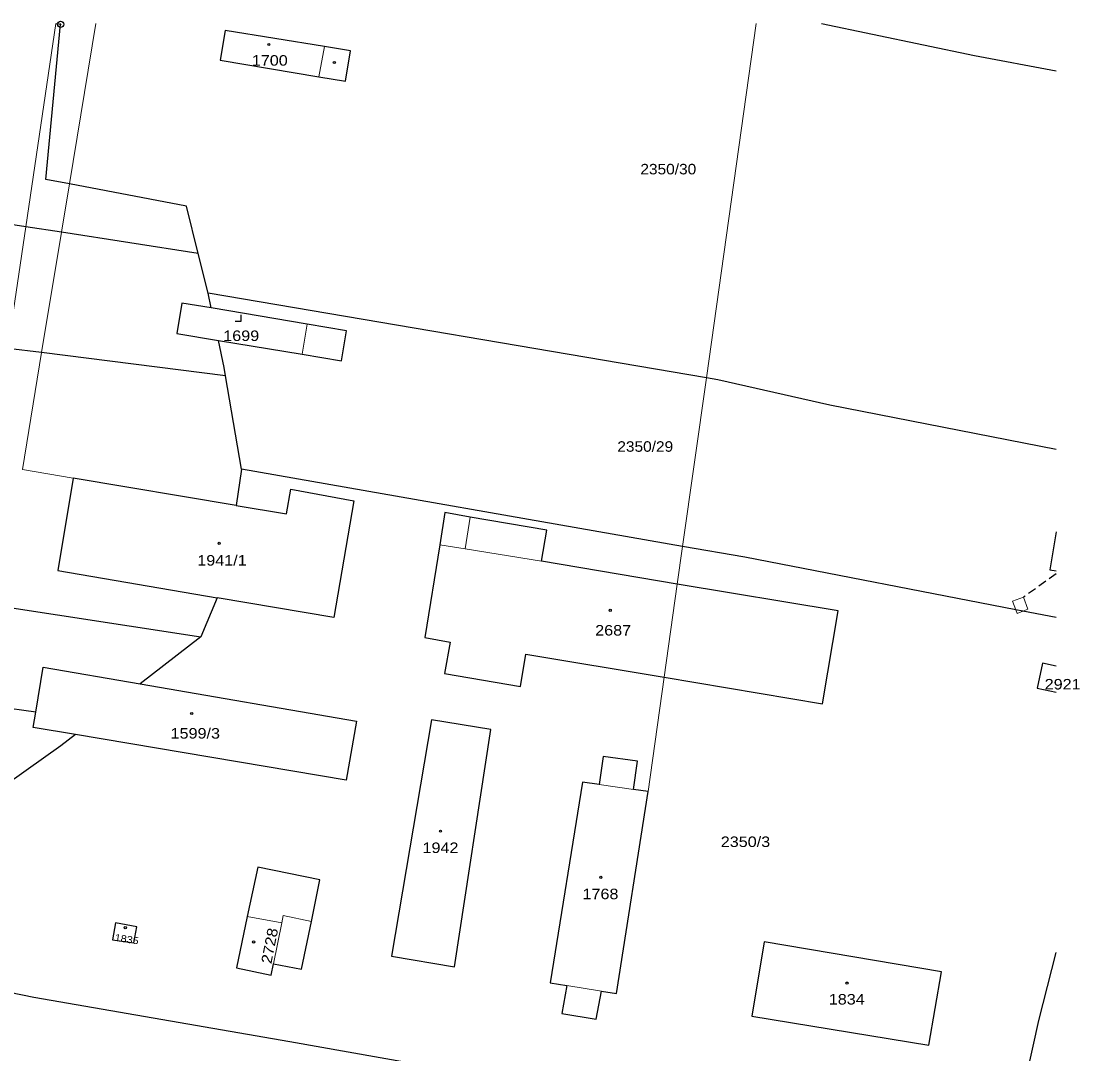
# Model space of a CAD drawing. Extents: x -652394 to -652006, y -1024262 to -1023975.
# Drawn here: x -652176.9 to -652005.6, y -1024142.7 to -1023975.5 of the extents above; entities that cross this region are included whole.
import ezdxf

# ---------------------------------------------------------------- set-up
doc = ezdxf.new("R2010")
doc.units = 0
doc.header["$LTSCALE"] = 0.46
doc.linetypes.add('MEDIUM_DASHED', pattern=[4.5, 3, -1.5])
doc.layers.add('63', color=7, linetype='Continuous', lineweight=25)

msp = doc.modelspace()

# ---------------------------------------------------------------- linework, layer by layer
at = {"layer": '63', "lineweight": 13}
for p, q in [((-652176.19, -1024008.82), (-652171.333, -1023975.941)), ((-652169.11, -1024001.89), (-652164.834, -1023975.941)), ((-652066.03, -1024033.3), (-652057.952, -1023975.941)), ((-652128.74, -1023984.54), (-652127.84, -1023979.66)), ((-652170.4, -1024009.72), (-652169.11, -1024001.89)), ((-652179.1, -1024028.51), (-652176.19, -1024008.82)), ((-652131.45, -1024029.47), (-652130.66, -1024024.59)), ((-652069.87, -1024060.56), (-652066.03, -1024033.3)), ((-652176.73, -1024048.12), (-652168.53, -1024049.53)), ((-652105.08, -1024060.94), (-652092.7, -1024062.94)), ((-652070.73, -1024066.65), (-652069.87, -1024060.56)), ((-652072.86, -1024081.74), (-652070.73, -1024066.65)), ((-652016.48, -1024069.45), (-652014.7, -1024068.79)), ((-652016.48, -1024069.45), (-652015.97, -1024070.81)), ((-652014.7, -1024068.79), (-652013.98, -1024070.71)), ((-652014.8, -1024071.04), (-652013.98, -1024070.71)), ((-652075.46, -1024100.21), (-652072.86, -1024081.74)), ((-652083.38, -1024099.11), (-652077.81, -1024099.89)), ((-652140.32, -1024120.48), (-652134.75, -1024121.52)), ((-652136.08, -1024128.14), (-652134.75, -1024121.52)), ((-652088.63, -1024131.64), (-652083.02, -1024132.53))]:
    msp.add_line(p, q, dxfattribs=at)
at = {"layer": '63'}
for p, q in [((-652171.192, -1023975.941), (-652170.54, -1023976.04)), ((-652170.54, -1023976.04), (-652170.53, -1023975.941)), ((-652146.66, -1024019.59), (-652148.27, -1024013.13)), ((-652146.15, -1024021.97), (-652146.66, -1024019.59)), ((-652141.25, -1024048.05), (-652143.83, -1024032.94)), ((-652142.12, -1024053.95), (-652133.96, -1024055.31)), ((-652009.403, -1024058.19), (-652010.45, -1024064.33)), ((-652010.45, -1024064.33), (-652009.403, -1024064.501)), ((-652126.33, -1024072.09), (-652145.21, -1024068.87)), ((-652174.55, -1024087.4), (-652190.57, -1024085.1))]:
    msp.add_line(p, q, dxfattribs=at)
at = {"layer": '63', "linetype": 'MEDIUM_DASHED'}
msp.add_line((-652009.403, -1024064.997), (-652014.7, -1024068.79), dxfattribs=at)
at = {"layer": '63'}
for points in [[(-652148.27, -1024013.13), (-652170.4, -1024009.72), (-652176.19, -1024008.82), (-652243.97, -1023998.36), (-652254.55, -1023996.87), (-652255.534, -1023975.941)], [(-652148.27, -1024013.13), (-652150.18, -1024005.47), (-652169.11, -1024001.89), (-652172.93, -1024001.16), (-652170.54, -1023976.04)], [(-652047.402, -1023975.941), (-652022.66, -1023981.11), (-652009.403, -1023983.604)], [(-652143.83, -1024032.94), (-652173.61, -1024029.2), (-652179.1, -1024028.51), (-652205.95, -1024025.14), (-652253.52, -1024018.67)], [(-652009.403, -1024044.899), (-652046.04, -1024037.7), (-652064.17, -1024033.62), (-652066.03, -1024033.3), (-652146.66, -1024019.59)], [(-652146.15, -1024021.97), (-652150.9, -1024021.17), (-652151.72, -1024026.09), (-652145.01, -1024027.21)], [(-652145.01, -1024027.21), (-652131.45, -1024029.47), (-652125.06, -1024030.53), (-652124.28, -1024025.67), (-652130.66, -1024024.59), (-652146.15, -1024021.97)], [(-652142.301, -1024024.08), (-652141.3, -1024024.08), (-652141.3, -1024023.08)], [(-652143.83, -1024032.94), (-652144.06, -1024031.61), (-652145.01, -1024027.21)], [(-652009.403, -1024072.085), (-652014.8, -1024071.04), (-652015.97, -1024070.81), (-652059.83, -1024062.32), (-652069.87, -1024060.56), (-652141.25, -1024048.05), (-652142.12, -1024053.95)], [(-652142.12, -1024053.95), (-652168.53, -1024049.53), (-652171.01, -1024064.48), (-652145.21, -1024068.87)], [(-652133.96, -1024055.31), (-652133.29, -1024051.32), (-652123.09, -1024053.17), (-652126.33, -1024072.09)], [(-652251.57, -1024060.11), (-652245.35, -1024060.77), (-652231.31, -1024062.37), (-652216.77, -1024064.61), (-652147.85, -1024075.21)], [(-652145.21, -1024068.87), (-652147.85, -1024075.21), (-652157.64, -1024082.83)], [(-652174.55, -1024087.4), (-652173.34, -1024080.12), (-652157.64, -1024082.83)], [(-652009.403, -1024079.928), (-652011.64, -1024079.45), (-652012.51, -1024083.5), (-652009.403, -1024084.169)], [(-652157.64, -1024082.83), (-652122.66, -1024088.87), (-652124.33, -1024098.39), (-652168.15, -1024091.02)], [(-652168.15, -1024091.02), (-652174.96, -1024089.87), (-652174.55, -1024087.4)], [(-652168.15, -1024091.02), (-652170.52, -1024092.87), (-652182.16, -1024101.09), (-652189.3, -1024108.53), (-652196.06, -1024116.16)], [(-652009.403, -1024157.766), (-652016.24, -1024155.4), (-652012.21, -1024137.29), (-652009.403, -1024126.324)], [(-652198.26, -1024128.72), (-652174.89, -1024133.55), (-652133.42, -1024140.71), (-652109.38, -1024144.99), (-652070.02, -1024157.71), (-652064.99, -1024159.32), (-652012.85, -1024174.11)]]:
    msp.add_lwpolyline(points, dxfattribs=at)
for points in [[(-652128.74, -1023984.54), (-652124.42, -1023985.27), (-652123.6, -1023980.35), (-652127.84, -1023979.66), (-652143.89, -1023977.05), (-652144.74, -1023981.85)], [(-652070.73, -1024066.65), (-652092.7, -1024062.94), (-652091.86, -1024057.95), (-652104.26, -1024055.81), (-652108.34, -1024055.1), (-652109.18, -1024060.29), (-652111.6, -1024075.33), (-652107.5, -1024076.04), (-652108.39, -1024081.16), (-652096.11, -1024083.25), (-652095.24, -1024078), (-652072.86, -1024081.74), (-652047.23, -1024086.02), (-652044.71, -1024070.97)], [(-652110.51, -1024088.61), (-652116.97, -1024126.91), (-652106.81, -1024128.64), (-652100.89, -1024090.21)], [(-652082.73, -1024094.57), (-652083.38, -1024099.11), (-652086.05, -1024098.75), (-652091.3, -1024131.22), (-652088.63, -1024131.64), (-652089.41, -1024136.19), (-652083.89, -1024137.11), (-652083.02, -1024132.53), (-652080.6, -1024132.91), (-652075.46, -1024100.21), (-652077.81, -1024099.89), (-652077.19, -1024095.35)], [(-652131.53, -1024129.02), (-652129.95, -1024121.27), (-652128.57, -1024114.51), (-652138.64, -1024112.49), (-652140.32, -1024120.48), (-652142.07, -1024128.8), (-652136.45, -1024129.95), (-652136.08, -1024128.14)], [(-652161.65, -1024121.5), (-652162.16, -1024124.23), (-652158.71, -1024124.75), (-652158.2, -1024122.15)], [(-652030, -1024141.32), (-652027.99, -1024129.45), (-652056.7, -1024124.59), (-652058.69, -1024136.59)]]:
    msp.add_lwpolyline(points, close=True, dxfattribs=at)
at = {"layer": '63', "lineweight": 13}
for points in [[(-652128.74, -1023984.54), (-652124.42, -1023985.27), (-652123.6, -1023980.35), (-652127.84, -1023979.66), (-652143.89, -1023977.05), (-652144.74, -1023981.85)], [(-652144.74, -1023981.85), (-652128.74, -1023984.54), (-652127.84, -1023979.66), (-652143.89, -1023977.05)], [(-652243.97, -1023998.36), (-652254.55, -1023996.87), (-652253.52, -1024018.67), (-652205.95, -1024025.14), (-652179.1, -1024028.51), (-652173.61, -1024029.2), (-652143.83, -1024032.94), (-652144.06, -1024031.61), (-652145.01, -1024027.21), (-652151.72, -1024026.09), (-652150.9, -1024021.17), (-652146.15, -1024021.97), (-652146.66, -1024019.59), (-652148.27, -1024013.13), (-652170.4, -1024009.72), (-652176.19, -1024008.82)], [(-652245.35, -1024060.77), (-652231.31, -1024062.37), (-652216.77, -1024064.61), (-652147.85, -1024075.21), (-652145.21, -1024068.87), (-652171.01, -1024064.48), (-652168.53, -1024049.53), (-652142.12, -1024053.95), (-652141.25, -1024048.05), (-652143.83, -1024032.94), (-652173.61, -1024029.2), (-652179.1, -1024028.51), (-652205.95, -1024025.14), (-652253.52, -1024018.67), (-652252.69, -1024036.32), (-652251.57, -1024060.11)], [(-652130.66, -1024024.59), (-652146.15, -1024021.97), (-652150.9, -1024021.17), (-652151.72, -1024026.09), (-652145.01, -1024027.21), (-652131.45, -1024029.47), (-652125.06, -1024030.53), (-652124.28, -1024025.67)], [(-652145.21, -1024068.87), (-652126.33, -1024072.09), (-652123.09, -1024053.17), (-652133.29, -1024051.32), (-652133.96, -1024055.31), (-652142.12, -1024053.95), (-652168.53, -1024049.53), (-652171.01, -1024064.48)], [(-652171.01, -1024064.48), (-652145.21, -1024068.87), (-652126.33, -1024072.09), (-652123.09, -1024053.17), (-652133.29, -1024051.32), (-652133.96, -1024055.31), (-652142.12, -1024053.95), (-652168.53, -1024049.53)], [(-652070.73, -1024066.65), (-652092.7, -1024062.94), (-652091.86, -1024057.95), (-652104.26, -1024055.81), (-652108.34, -1024055.1), (-652109.18, -1024060.29), (-652111.6, -1024075.33), (-652107.5, -1024076.04), (-652108.39, -1024081.16), (-652096.11, -1024083.25), (-652095.24, -1024078), (-652072.86, -1024081.74), (-652047.23, -1024086.02), (-652044.71, -1024070.97)], [(-652157.64, -1024082.83), (-652147.85, -1024075.21), (-652216.77, -1024064.61), (-652231.31, -1024062.37), (-652245.35, -1024060.77), (-652251.57, -1024060.11), (-652251.01, -1024072.09), (-652218.15, -1024072.78), (-652189.16, -1024077.6), (-652190.57, -1024085.1), (-652174.55, -1024087.4), (-652173.34, -1024080.12)], [(-652111.6, -1024075.33), (-652107.5, -1024076.04), (-652108.39, -1024081.16), (-652096.11, -1024083.25), (-652095.24, -1024078), (-652072.86, -1024081.74), (-652070.73, -1024066.65), (-652092.7, -1024062.94), (-652105.08, -1024060.94), (-652109.18, -1024060.29)], [(-652168.15, -1024091.02), (-652124.33, -1024098.39), (-652122.66, -1024088.87), (-652157.64, -1024082.83), (-652173.34, -1024080.12), (-652174.55, -1024087.4), (-652174.96, -1024089.87)], [(-652174.96, -1024089.87), (-652168.15, -1024091.02), (-652124.33, -1024098.39), (-652122.66, -1024088.87), (-652157.64, -1024082.83), (-652173.34, -1024080.12), (-652174.55, -1024087.4)], [(-652168.15, -1024091.02), (-652174.96, -1024089.87), (-652174.55, -1024087.4), (-652190.57, -1024085.1), (-652190.99, -1024087.34), (-652219.82, -1024082.64), (-652222.47, -1024098.26), (-652193.37, -1024103.11), (-652195.04, -1024112.97), (-652195.63, -1024112.89), (-652196.06, -1024116.16), (-652189.3, -1024108.53), (-652182.16, -1024101.09), (-652170.52, -1024092.87)], [(-652110.51, -1024088.61), (-652116.97, -1024126.91), (-652106.81, -1024128.64), (-652100.89, -1024090.21)], [(-652116.97, -1024126.91), (-652106.81, -1024128.64), (-652100.89, -1024090.21), (-652110.51, -1024088.61)], [(-652082.73, -1024094.57), (-652083.38, -1024099.11), (-652086.05, -1024098.75), (-652091.3, -1024131.22), (-652088.63, -1024131.64), (-652089.41, -1024136.19), (-652083.89, -1024137.11), (-652083.02, -1024132.53), (-652080.6, -1024132.91), (-652075.46, -1024100.21), (-652077.81, -1024099.89), (-652077.19, -1024095.35)], [(-652091.3, -1024131.22), (-652088.63, -1024131.64), (-652083.02, -1024132.53), (-652080.6, -1024132.91), (-652075.46, -1024100.21), (-652077.81, -1024099.89), (-652083.38, -1024099.11), (-652086.05, -1024098.75)], [(-652131.53, -1024129.02), (-652129.95, -1024121.27), (-652128.57, -1024114.51), (-652138.64, -1024112.49), (-652140.32, -1024120.48), (-652142.07, -1024128.8), (-652136.45, -1024129.95), (-652136.08, -1024128.14)], [(-652161.65, -1024121.5), (-652162.16, -1024124.23), (-652158.71, -1024124.75), (-652158.2, -1024122.15)], [(-652162.16, -1024124.23), (-652158.71, -1024124.75), (-652158.2, -1024122.15), (-652161.65, -1024121.5)], [(-652142.07, -1024128.8), (-652136.45, -1024129.95), (-652136.08, -1024128.14), (-652134.75, -1024121.52), (-652140.32, -1024120.48)], [(-652030, -1024141.32), (-652027.99, -1024129.45), (-652056.7, -1024124.59), (-652058.69, -1024136.59)], [(-652058.69, -1024136.59), (-652030, -1024141.32), (-652027.99, -1024129.45), (-652056.7, -1024124.59)]]:
    msp.add_lwpolyline(points, close=True, dxfattribs=at)
for points in [[(-652176.73, -1024048.12), (-652173.61, -1024029.2), (-652170.4, -1024009.72)], [(-652109.18, -1024060.29), (-652105.08, -1024060.94), (-652104.26, -1024055.81)], [(-652015.97, -1024070.81), (-652015.74, -1024071.42), (-652014.8, -1024071.04)], [(-652134.75, -1024121.52), (-652134.5, -1024120.3), (-652129.95, -1024121.27)], [(-652109.38, -1024144.99), (-652133.42, -1024140.71), (-652174.89, -1024133.55), (-652198.26, -1024128.72)]]:
    msp.add_lwpolyline(points, dxfattribs=at)
at = {"layer": '63'}
for centre, radius in [((-652170.54, -1023976.0399), 0.5), ((-652170.54, -1023976.0399), 0.0303), ((-652136.8368, -1023979.3092), 0.175), ((-652126.2368, -1023982.2292), 0.175), ((-652144.8768, -1024060.0592), 0.175), ((-652081.5868, -1024070.9092), 0.175), ((-652149.3168, -1024087.6192), 0.175), ((-652109.0568, -1024106.6592), 0.175), ((-652083.1168, -1024114.1392), 0.175), ((-652160.0668, -1024122.2692), 0.175), ((-652139.2968, -1024124.5892), 0.175), ((-652043.2568, -1024131.2492), 0.175)]:
    msp.add_circle(centre, radius, dxfattribs=at)

# ---------------------------------------------------------------- texts
for s, width, p in [('1700', 1.15, (-652139.597, -1023982.74)), ('2350/30', 1.1, (-652076.71, -1024000.34)), ('1699', 1.15, (-652144.217, -1024027.31)), ('2350/29', 1.1, (-652080.44, -1024045.24)), ('1941/1', 1.15, (-652148.42, -1024063.67)), ('2687', 1.15, (-652084.02, -1024074.99)), ('2921', 1.15, (-652011.277, -1024083.72)), ('1599/3', 1.15, (-652152.74, -1024091.67)), ('2350/3', 1.15, (-652063.7, -1024109.22)), ('1942', 1.15, (-652111.967, -1024110.19)), ('1768', 1.15, (-652086.077, -1024117.67)), ('1834', 1.15, (-652046.217, -1024134.72))]:
    msp.add_text(s, height=1.7, dxfattribs=dict(at, width=width)).set_placement(p)
at = {"layer": '63', "width": 1.15}
for s, height, rotation, p in [('1835', 1.14, 351, (-652161.849, -1024124.392)), ('2728', 1.7, 79, (-652136.434, -1024128.223))]:
    msp.add_text(s, height=height, rotation=rotation, dxfattribs=at).set_placement(p)

doc.saveas('drawing.dxf')
